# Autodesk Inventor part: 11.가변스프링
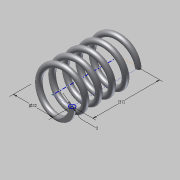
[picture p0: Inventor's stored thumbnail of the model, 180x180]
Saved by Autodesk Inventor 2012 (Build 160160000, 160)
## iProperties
Created: 2014-12
Part Number: 11.가변스프링
Material: Default
Document SubType Name: Modeling
Designer: HOME
Density: 1 g/cm^3
Mass: 2.37794 g
Surface Area: 32.4134 cm^2
Volume: 2.37794 cm^3
Author: HOME
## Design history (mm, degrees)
sketch "스케치1"
  geometry: L1 (0, 0)-(11, 0); L2 (11, 0)-(11, 36.411); L3 (11, 36.411)-(0, 36.411); L4 (0, 36.411)-(0, 0); C1 r 1.5 at (11, 0); 1 further point
  constraints: 8 end point, 2 coincident, 2 parallel, 1 centre point, 1 horizontal, 1 perpendicular
  dimensions: "d0" = 22 diameter of L2 L4; "d1" = 36.4112 distance of L1.end L2.end (derived); "d2" = 3 diameter of C1
feature "코일1" pitch "d3" = 10; turns "d5" = 5; dims "d4" = 36.4112 (= d1), "d6" = 0, angle "d7" = 90 deg, angle "d8" = 90 deg, "d9" = 0, "d10" = 0
sketch "스케치2"
  geometry: L1 (-12.5, 0)-(-9.5, 0) reference; 1 further point
  constraints: 1 horizontal alignment
extrude "돌출1" cut sketch "스케치2" stored distance "d11" = 10; taper "d12" = 0 deg
node "작업 평면1"
sketch "스케치3"
  geometry: L1 (-9.5, 0)-(-12.5, 0) reference; 1 further point
  constraints: 1 horizontal alignment
extrude "돌출2" cut sketch "스케치3" stored distance "d13" = 10; taper "d14" = 0 deg
node "솔리드1"
node "절단 모서리 투영1"
node "절단 모서리 투영2"
